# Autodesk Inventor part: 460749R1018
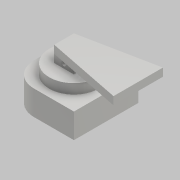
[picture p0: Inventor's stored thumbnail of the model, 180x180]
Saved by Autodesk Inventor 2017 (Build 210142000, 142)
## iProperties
Created: 2016-07
Part Number: 460749R1018
Material: Aluminum 6061
Document SubType Name: Modeling
Designer: Polytech
Density: 2.7 g/cm^3
Appearance: Aluminum - Flat
Mass: 1260.26 g
Surface Area: 611.154 cm^2
Volume: 466.762 cm^3
Author: Polytech
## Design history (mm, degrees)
sketch "Sketch1"
  geometry: C1 r 23 at (0, 0); 1 further point
  constraints: 1 centre point, 1 coincident
  dimensions: "d0" = 46 diameter of C1
extrude "Extrusion1" new body sketch "Sketch1" distance "d1" = 18; taper "d2" = 0 deg
sketch "Sketch2"
  geometry: L1 (-11.75, 48.75)-(48.75, 48.75); L2 (48.75, 48.75)-(48.75, -48.75); L3 (48.75, -48.75)-(-11.75, -48.75); L4 (-48.75, -11.75)-(-48.75, 11.75); L5 (-48.75, 48.75)-(48.75, -48.75); L6 (48.75, 48.75)-(-48.75, -48.75); A1 r 37 centre (-11.75, 11.75) between (-11.75, 48.75) and (-48.75, 11.75); A2 r 37 centre (-11.75, -11.75) between (-48.75, -11.75) and (-11.75, -48.75); 1 further point
  constraints: 12 end point, 4 point on circle, 4 point on line, 4 tangent, 2 centre point, 2 midpoint, 2 parallel, 1 equal radius, 1 horizontal, 1 perpendicular
  dimensions: "d3" = 97.5 distance of L2.end L6.end; "d4" = 97.5 distance of L1.end L2.end; "d5" = 37 radius of A1 (derived)
extrude "Extrusion2" join sketch "Sketch2" distance "d6" = 37.5; taper "d7" = 0 deg
sketch "Sketch3"
  geometry: C1 r 37.5 at (0, 0); 1 further point
  constraints: 1 centre point, 1 coincident
  dimensions: "d8" = 75 diameter of C1
extrude "Extrusion3" join sketch "Sketch3" distance "d9" = 15; taper "d10" = 0 deg
sketch "Sketch4"
  geometry: L1 (-15, 15)-(15, 15); L2 (15, 15)-(15, -15); L3 (15, -15)-(-15, -15); L4 (-15, -15)-(-15, 15); L5 (-15, 15)-(15, -15); L6 (15, 15)-(-15, -15); 1 further point
  constraints: 12 end point, 2 midpoint, 2 parallel, 1 horizontal, 1 perpendicular
  dimensions: "d11" = 30 distance of L2.end L3.end; "d12" = 30 distance of L1.end L2.end
extrude "Extrusion4" join sketch "Sketch4" distance "d13" = 12; taper "d14" = 0 deg
sketch "Sketch5"
  geometry: L1 (-15, 6)-(15, 6); L2 (15, 6)-(15, -6); L3 (15, -6)-(-15, -6); L4 (-15, -6)-(-15, 6); L5 (-15, 6)-(15, -6); L6 (15, 6)-(-15, -6); 1 further point
  constraints: 12 end point, 2 midpoint, 2 parallel, 1 horizontal, 1 perpendicular
  dimensions: "d15" = 30 distance of L2.end L3.end; "d16" = 12 distance of L1.end L2.end
extrude "Extrusion5" cut sketch "Sketch5" distance "d17" = 12; taper "d18" = 0 deg
sketch "Sketch6"
  geometry: L1 (52.5, 0)-(-22.5, 0) reference; C1 r 3 at (15, 6); 1 further point
  constraints: 1 centre point, 1 vertical alignment
  dimensions: "d19" = 6 diameter of C1; "d20" = 6 distance from line of L1 C1.centre
extrude "Extrusion6" cut sketch "Sketch6" stored distance "d21" = 12; taper "d22" = 0 deg
sketch "Sketch7"
  geometry: L1 (-15, 15)-(-15, -15); L2 (-15, -15)-(97.5, -37.5); L3 (97.5, -37.5)-(97.5, 37.5); L4 (97.5, 37.5)-(-15, 15); 4 further points
  constraints: 8 end point, 2 coincident, 1 horizontal alignment, 1 midpoint, 1 parallel, 1 vertical
  dimensions: "d23" = 97.5 horizontal distance of L2.end point (0, 0); "d24" = 75 distance of L2.end L3.end
extrude "Extrusion7" join sketch "Sketch7" distance "d25" = 12; taper "d26" = 0 deg
sketch "Sketch8"
  geometry: C1 r 23 at (0, 0); 1 further point
  constraints: 1 centre point, 1 coincident
  dimensions: "d27" = 46 diameter of C1
extrude "Extrusion8" cut sketch "Sketch8" distance "d28" = 24.5; taper "d29" = 0 deg
body "Solid1"
